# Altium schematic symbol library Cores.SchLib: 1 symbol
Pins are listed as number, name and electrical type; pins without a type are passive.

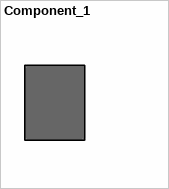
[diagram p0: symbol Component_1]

## Component_1
designator CORE?, comment Used in BOM report
CompType: Used in some BOM reports.  Useful for finding later.
footprint PCBComponent_1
